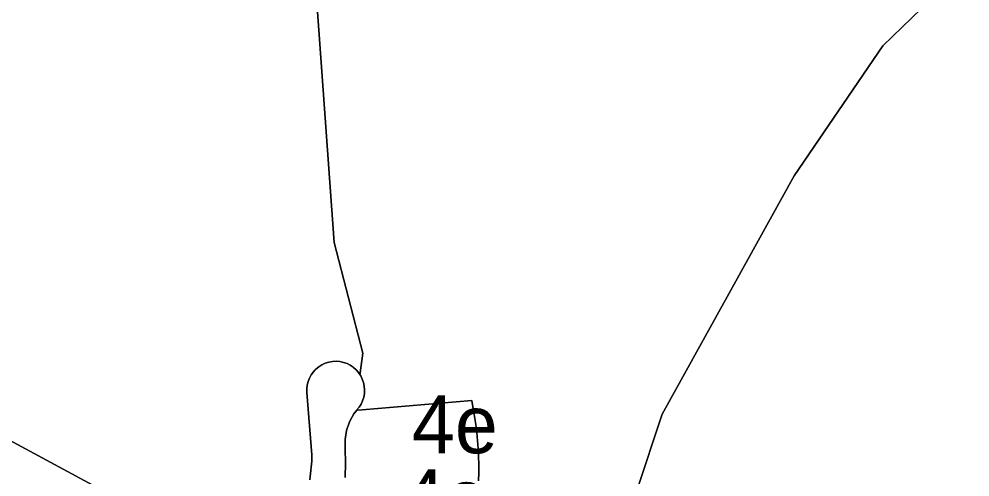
# Model space of a CAD drawing. Extents: x 598968 to 613553, y 4409678 to 4430833.
# Drawn here: x 609700.3 to 609897.7, y 4416621 to 4416716 of the extents above; entities that cross this region are included whole.
import ezdxf

# ---------------------------------------------------------------- set-up
doc = ezdxf.new("R2010")
doc.units = 0
for name, color, linetype in [('1', 7, 'Continuous'), ('4e. Sector de consolidació - ANNEX III A', 7, 'Continuous'), ('Sòl Rústic Protegit', 7, 'Continuous'), ('Sòl Rústic Protegit - Alt Nivell de Protecció', 7, 'Continuous')]:
    doc.layers.add(name, color=color, linetype=linetype)

msp = doc.modelspace()

# ---------------------------------------------------------------- linework, layer by layer
at = {"layer": '1'}
msp.add_lwpolyline([(609767.981, 4416620.8796), (609768.1014, 4416623.891), (609768.0121, 4416626.9036), (609767.9875, 4416628.7915), (609768.2846, 4416630.6563), (609768.8949, 4416632.4432), (609769.8005, 4416634.1001), (609770.4114, 4416634.8691), (609770.3874, 4416634.8671), (609770.8801, 4416635.459), (609771.2936, 4416636.1089), (609771.62, 4416636.8065), (609771.8544, 4416637.5401), (609771.9929, 4416638.2978), (609772.0332, 4416639.0668), (609771.9747, 4416639.8348), (609771.8182, 4416640.5889), (609771.5664, 4416641.3167), (609771.2235, 4416642.0063), (609771.0451, 4416642.2727), (609770.795, 4416642.6463), (609770.2881, 4416643.2262), (609769.7111, 4416643.7362), (609769.6677, 4416643.7656), (609769.0734, 4416644.1683), (609768.3857, 4416644.515), (609767.6593, 4416644.7708), (609766.906, 4416644.9314), (609766.1384, 4416644.9943), (609765.369, 4416644.9583), (609764.6107, 4416644.8239), (609763.8758, 4416644.5936), (609763.1764, 4416644.271), (609762.5241, 4416643.8614), (609761.9297, 4416643.3717), (609761.7924, 4416643.2254), (609761.4028, 4416642.8099), (609760.9523, 4416642.1852), (609760.5855, 4416641.508), (609760.3084, 4416640.7894), (609760.1258, 4416640.0412), (609760.0404, 4416639.2757), (609760.0538, 4416638.5057), (609761.1103, 4416625.5977), (609761.0838, 4416624.9486), (609761.0478, 4416624.3001), (609761.0025, 4416623.652), (609760.9477, 4416623.0047), (609760.8835, 4416622.3583), (609760.8099, 4416621.7129), (609760.727, 4416621.0686), (609760.6346, 4416620.4255)], dxfattribs=at)
at = {"layer": '4e. Sector de consolidació - ANNEX III A'}
msp.add_lwpolyline([(609795.6989, 4416620.2162), (609795.7339, 4416621.8901), (609795.7295, 4416623.5644), (609795.6858, 4416625.238), (609795.6028, 4416626.9101), (609795.4806, 4416628.58), (609795.3192, 4416630.2465), (609795.1187, 4416631.9086), (609794.8792, 4416633.5656), (609794.6009, 4416635.2166), (609794.3799, 4416636.3626), (609794.2839, 4416636.8606), (609771.5137, 4416634.9611), (609770.4114, 4416634.8691), (609769.8005, 4416634.1001), (609768.8949, 4416632.4432), (609768.2846, 4416630.6563), (609767.9875, 4416628.7915), (609768.0121, 4416626.9036), (609768.1014, 4416623.891), (609767.981, 4416620.8796)], dxfattribs=at)
at = {"layer": 'Sòl Rústic Protegit'}
for points in [[(609760.6547, 4416739.6844), (609765.7173, 4416669.6844), (609771.6547, 4416646.6844), (609771.0917, 4416642.6372), (609771.0451, 4416642.2727), (609771.2235, 4416642.0063), (609771.5664, 4416641.3167), (609771.8182, 4416640.5889), (609771.9747, 4416639.8348), (609772.0332, 4416639.0668), (609771.9929, 4416638.2978), (609771.8544, 4416637.5401), (609771.62, 4416636.8065), (609771.2936, 4416636.1089), (609770.8801, 4416635.459), (609770.3874, 4416634.8671), (609770.4114, 4416634.8691), (609771.5137, 4416634.9611), (609794.2839, 4416636.8606), (609794.3799, 4416636.3626), (609794.6009, 4416635.2166), (609794.8792, 4416633.5656), (609795.1187, 4416631.9086), (609795.3192, 4416630.2465), (609795.4806, 4416628.58), (609795.6028, 4416626.9101), (609795.6858, 4416625.238), (609795.7295, 4416623.5644), (609795.7339, 4416621.8901), (609795.6989, 4416620.2162)], [(609828.4927, 4416618.0098), (609833.8051, 4416634.0098), (609861.2427, 4416683.5098), (609879.6801, 4416710.5098), (609897.7427, 4416728.0098)], [(609695.3015, 4416598.1863), (609700.8325, 4416599.6309), (609706.2968, 4416601.8416), (609712.2841, 4416604.6221), (609715.4686, 4416606.1721), (609720.4912, 4416608.6759), (609723.4973, 4416610.0531), (609725.2174, 4416610.6926), (609727.0271, 4416611.1505), (609729.1558, 4416611.3636), (609730.549, 4416611.3357), (609731.4222, 4416611.1387), (609728.7179, 4416612.234), (609709.4489, 4416622.5932), (609597.0905, 4416683.2)]]:
    msp.add_lwpolyline(points, dxfattribs=at)
at = {"layer": 'Sòl Rústic Protegit - Alt Nivell de Protecció'}
for points in [[(609760.6346, 4416620.4255), (609760.727, 4416621.0686), (609760.8099, 4416621.7129), (609760.8835, 4416622.3583), (609760.9477, 4416623.0047), (609761.0025, 4416623.652), (609761.0478, 4416624.3001), (609761.0838, 4416624.9486), (609761.1103, 4416625.5977), (609760.0538, 4416638.5057), (609760.0404, 4416639.2757), (609760.1258, 4416640.0412), (609760.3084, 4416640.7894), (609760.5855, 4416641.508), (609760.9523, 4416642.1852), (609761.4028, 4416642.8099), (609761.7924, 4416643.2254), (609761.9297, 4416643.3717), (609762.5241, 4416643.8614), (609763.1764, 4416644.271), (609763.8758, 4416644.5936), (609764.6107, 4416644.8239), (609765.369, 4416644.9583), (609766.1384, 4416644.9943), (609766.906, 4416644.9314), (609767.6593, 4416644.7708), (609768.3857, 4416644.515), (609769.0734, 4416644.1683), (609769.6677, 4416643.7656), (609769.7111, 4416643.7362), (609770.2881, 4416643.2262), (609770.795, 4416642.6463), (609771.0451, 4416642.2727), (609771.0917, 4416642.6372), (609771.6547, 4416646.6844), (609765.7173, 4416669.6844), (609760.6547, 4416739.6844)], [(609897.7427, 4416728.0098), (609879.6801, 4416710.5098), (609861.2427, 4416683.5098), (609833.8051, 4416634.0098), (609828.4927, 4416618.0098)], [(609597.0905, 4416683.2), (609709.4489, 4416622.5932), (609728.7179, 4416612.234)]]:
    msp.add_lwpolyline(points, dxfattribs=at)

# ---------------------------------------------------------------- texts
at = {"layer": '4e. Sector de consolidació - ANNEX III A'}
for p in [(609781.8575, 4416625.9108), (609779.8057, 4416610.6052)]:
    msp.add_text('4e', height=12, dxfattribs=at).set_placement(p)

doc.saveas('drawing.dxf')
